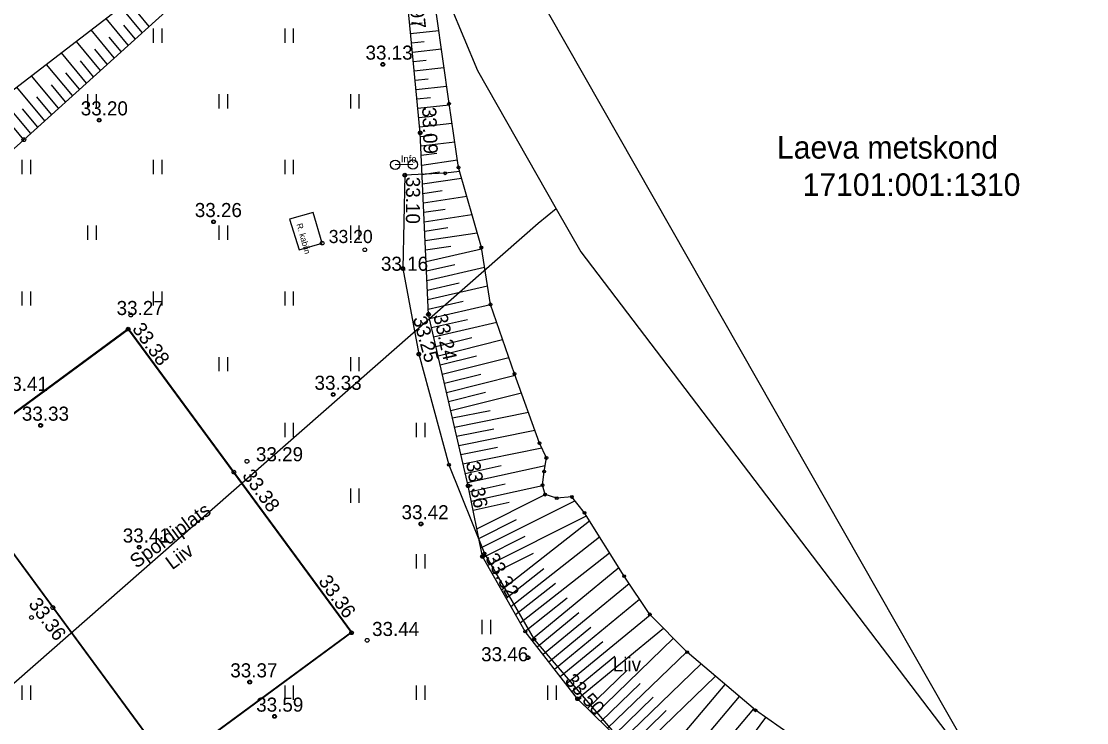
# Model space of a CAD drawing. Extents: x 641898 to 642452, y 6471715 to 6472255.
# Drawn here: x 642067.2 to 642123.9, y 6472154.8 to 6472192.2 of the extents above; entities that cross this region are included whole.
import ezdxf

# ---------------------------------------------------------------- set-up
doc = ezdxf.new("R2010")
doc.units = 0
for name, color, linetype in [('HALJASTUS', 7, 'Continuous'), ('KORGUS-EH2000', 7, 'Continuous'), ('MOOTMPUNKT', 7, 'Continuous'), ('MOOTPIIR', 7, 'Continuous'), ('PIIR', 7, 'Continuous'), ('RAJATIS', 7, 'Continuous'), ('RELJEEF', 7, 'Continuous'), ('VEEKOGU', 7, 'Continuous')]:
    doc.layers.add(name, color=color, linetype=linetype)

msp = doc.modelspace()

# ---------------------------------------------------------------- linework, layer by layer
at = {"layer": 'HALJASTUS'}
for p, q in [((642074.225, 6472191.782), (642074.225, 6472191.021)), ((642074.68, 6472191.782), (642074.68, 6472191.021)), ((642081.225, 6472191.782), (642081.225, 6472191.021)), ((642081.68, 6472191.782), (642081.68, 6472191.021)), ((642070.725, 6472188.282), (642070.725, 6472187.521)), ((642071.18, 6472188.282), (642071.18, 6472187.521)), ((642077.725, 6472188.282), (642077.725, 6472187.521)), ((642078.18, 6472188.282), (642078.18, 6472187.521)), ((642084.725, 6472188.282), (642084.725, 6472187.521)), ((642085.18, 6472188.282), (642085.18, 6472187.521)), ((642067.225, 6472184.782), (642067.225, 6472184.021)), ((642067.68, 6472184.782), (642067.68, 6472184.021)), ((642074.225, 6472184.782), (642074.225, 6472184.021)), ((642074.68, 6472184.782), (642074.68, 6472184.021)), ((642081.225, 6472184.782), (642081.225, 6472184.021)), ((642081.68, 6472184.782), (642081.68, 6472184.021)), ((642070.725, 6472181.282), (642070.725, 6472180.521)), ((642071.18, 6472181.282), (642071.18, 6472180.521)), ((642077.725, 6472181.282), (642077.725, 6472180.521)), ((642078.18, 6472181.282), (642078.18, 6472180.521)), ((642084.725, 6472181.282), (642084.725, 6472180.521)), ((642085.18, 6472181.282), (642085.18, 6472180.521)), ((642067.225, 6472177.782), (642067.225, 6472177.021)), ((642067.68, 6472177.782), (642067.68, 6472177.021)), ((642074.225, 6472177.782), (642074.225, 6472177.021)), ((642074.68, 6472177.782), (642074.68, 6472177.021)), ((642081.225, 6472177.782), (642081.225, 6472177.021)), ((642081.68, 6472177.782), (642081.68, 6472177.021)), ((642077.725, 6472174.282), (642077.725, 6472173.521)), ((642078.18, 6472174.282), (642078.18, 6472173.521)), ((642084.725, 6472174.282), (642084.725, 6472173.521)), ((642085.18, 6472174.282), (642085.18, 6472173.521)), ((642081.225, 6472170.782), (642081.225, 6472170.021)), ((642081.68, 6472170.782), (642081.68, 6472170.021)), ((642088.225, 6472170.782), (642088.225, 6472170.021)), ((642088.68, 6472170.782), (642088.68, 6472170.021)), ((642084.725, 6472167.282), (642084.725, 6472166.521)), ((642085.18, 6472167.282), (642085.18, 6472166.521)), ((642088.225, 6472163.782), (642088.225, 6472163.021)), ((642088.68, 6472163.782), (642088.68, 6472163.021)), ((642091.725, 6472160.282), (642091.725, 6472159.521)), ((642092.18, 6472160.282), (642092.18, 6472159.521)), ((642067.225, 6472156.782), (642067.225, 6472156.021)), ((642067.68, 6472156.782), (642067.68, 6472156.021)), ((642081.225, 6472156.782), (642081.225, 6472156.021)), ((642081.68, 6472156.782), (642081.68, 6472156.021)), ((642088.225, 6472156.782), (642088.225, 6472156.021)), ((642088.68, 6472156.782), (642088.68, 6472156.021)), ((642095.225, 6472156.782), (642095.225, 6472156.021)), ((642095.68, 6472156.782), (642095.68, 6472156.021))]:
    msp.add_line(p, q, dxfattribs=at)
msp.add_lwpolyline([(642090.544, 6472184.173), (642089.776, 6472184.072), (642087.626, 6472183.976), (642087.514, 6472178.998), (642088.366, 6472174.432), (642089.975, 6472168.544), (642091.871, 6472163.809), (642094.517, 6472159.241), (642098.776, 6472154.266), (642105.061, 6472148.666), (642112.911, 6472148.999), (642114.406, 6472149.64)], dxfattribs=at)
at = {"layer": 'KORGUS-EH2000'}
for centre in [(642086.452, 6472189.876), (642071.346, 6472186.906), (642067.331, 6472185.862), (642088.445, 6472186.228), (642087.626, 6472183.976), (642077.439, 6472181.489), (642083.221, 6472180.354), (642085.489, 6472179.997), (642087.514, 6472178.998), (642073.032, 6472176.519), (642088.882, 6472176.556), (642072.887, 6472175.77), (642088.366, 6472174.432), (642083.812, 6472172.286), (642068.226, 6472170.64), (642079.215, 6472168.728), (642078.519, 6472168.152), (642090.992, 6472167.424), (642088.483, 6472165.389), (642073.475, 6472164.147), (642091.756, 6472163.65), (642068.878, 6472160.93), (642067.74, 6472160.405), (642084.787, 6472159.593), (642085.62, 6472159.191), (642094.182, 6472158.265), (642079.361, 6472156.965), (642096.824, 6472156.077), (642080.687, 6472155.138)]:
    msp.add_circle(centre, 0.1, dxfattribs=at)
at = {"layer": 'MOOTMPUNKT'}
for centre in [(642086.452, 6472189.876), (642089.978, 6472187.781), (642071.346, 6472186.906), (642088.445, 6472186.228), (642090.483, 6472184.387), (642087.626, 6472183.976), (642089.776, 6472184.072), (642077.439, 6472181.489), (642091.698, 6472180.112), (642087.514, 6472178.998), (642092.187, 6472177.087), (642088.882, 6472176.556), (642072.875, 6472175.747), (642088.366, 6472174.432), (642093.463, 6472173.395), (642083.812, 6472172.286), (642068.226, 6472170.64), (642094.796, 6472169.693), (642095.162, 6472168.903), (642089.975, 6472168.544), (642095.04, 6472168.192), (642090.992, 6472167.424), (642094.951, 6472167.46), (642095.102, 6472166.95), (642095.71, 6472166.763), (642096.522, 6472166.827), (642097.188, 6472165.98), (642088.483, 6472165.389), (642073.475, 6472164.147), (642091.756, 6472163.65), (642091.871, 6472163.809), (642099.309, 6472162.605), (642100.668, 6472160.571), (642084.776, 6472159.609), (642094.039, 6472159.656), (642094.517, 6472159.241), (642102.657, 6472158.561), (642094.182, 6472158.265), (642079.361, 6472156.965), (642096.824, 6472156.077), (642080.687, 6472155.138), (642106.307, 6472155.459)]:
    msp.add_circle(centre, 0.075, dxfattribs=at)
at = {"layer": 'MOOTPIIR'}
msp.add_lwpolyline([(642014.306, 6472085.384), (642027.67, 6472104.979), (642055.501, 6472084.843), (642081.563, 6472094.262), (642123.938, 6472142.273), (642065.721, 6472244.475), (642008.922, 6472196.948), (642003.347, 6472200.453), (641979.65, 6472162.756), (641979.65, 6472162.756), (641986.045, 6472158.736), (642004.269, 6472142.365), (641987.048, 6472123.488), (641970.482, 6472097.889), (641986.758, 6472084.396)], close=True, dxfattribs=at)
at = {"layer": 'PIIR'}
for p, q in [((642090.03, 6472193.03), (642091.5, 6472189.54)), ((642091.5, 6472189.54), (642095.69, 6472182.18)), ((642095.69, 6472182.18), (642094.72, 6472181.39)), ((642095.69, 6472182.18), (642097, 6472179.89)), ((642094.72, 6472181.39), (642016.19, 6472112.51)), ((642097, 6472179.89), (642121.79, 6472147.29))]:
    msp.add_line(p, q, dxfattribs=at)
at = {"layer": 'RAJATIS'}
for points in [[(642088.054, 6472184.539), (642087.113, 6472184.528)], [(642081.989, 6472179.992), (642083.221, 6472180.354), (642082.742, 6472181.977), (642081.489, 6472181.633), (642081.989, 6472179.992)], [(642084.764, 6472159.611), (642075.113, 6472152.507), (642063.231, 6472168.648), (642072.882, 6472175.752), (642084.764, 6472159.611)]]:
    msp.add_lwpolyline(points, dxfattribs=at)
msp.add_lwpolyline([(642072.888, 6472175.794), (642084.806, 6472159.604), (642075.107, 6472152.465), (642063.189, 6472168.655)], close=True, dxfattribs=at)
for centre in [(642087.113, 6472184.528), (642088.054, 6472184.539)]:
    msp.add_circle(centre, 0.25, dxfattribs=at)
at = {"layer": 'RELJEEF'}
for p, q in [((642073.634, 6472191.565), (642072.509, 6472192.93)), ((642072.891, 6472190.893), (642071.716, 6472192.32)), ((642074.005, 6472191.901), (642073.429, 6472192.599)), ((642072.149, 6472190.221), (642070.923, 6472191.709)), ((642073.263, 6472191.229), (642072.658, 6472191.963)), ((642087.884, 6472192.017), (642088.542, 6472192.09)), ((642087.932, 6472191.519), (642089.43, 6472191.685)), ((642071.407, 6472189.55), (642070.13, 6472191.099)), ((642072.52, 6472190.557), (642071.886, 6472191.327)), ((642087.98, 6472191.022), (642088.652, 6472191.096)), ((642070.665, 6472188.878), (642069.337, 6472190.489)), ((642071.778, 6472189.886), (642071.114, 6472190.691)), ((642088.029, 6472190.524), (642089.569, 6472190.695)), ((642069.926, 6472188.21), (642068.541, 6472189.876)), ((642071.036, 6472189.214), (642070.342, 6472190.055)), ((642088.077, 6472190.026), (642088.762, 6472190.102)), ((642069.184, 6472187.538), (642067.748, 6472189.266)), ((642070.297, 6472188.546), (642069.571, 6472189.419)), ((642088.125, 6472189.528), (642089.708, 6472189.704)), ((642069.555, 6472187.874), (642068.802, 6472188.78)), ((642088.174, 6472189.027), (642088.874, 6472189.108)), ((642088.222, 6472188.529), (642089.847, 6472188.718)), ((642068.444, 6472186.869), (642066.952, 6472188.653)), ((642068.813, 6472187.203), (642068.033, 6472188.141)), ((642067.702, 6472186.198), (642066.159, 6472188.043)), ((642088.27, 6472188.032), (642088.989, 6472188.115)), ((642088.318, 6472187.534), (642089.986, 6472187.727)), ((642068.073, 6472186.534), (642067.265, 6472187.5)), ((642088.367, 6472187.036), (642089.104, 6472187.122)), ((642067.331, 6472185.862), (642066.498, 6472186.858)), ((642088.415, 6472186.538), (642090.133, 6472186.738)), ((642088.454, 6472186.039), (642089.22, 6472186.128)), ((642088.476, 6472185.539), (642090.28, 6472185.748)), ((642088.499, 6472185.038), (642089.335, 6472185.135)), ((642088.523, 6472184.507), (642090.423, 6472184.794)), ((642088.545, 6472184.005), (642089.47, 6472184.144)), ((642088.568, 6472183.503), (642090.645, 6472183.816)), ((642088.591, 6472183.001), (642089.619, 6472183.155)), ((642088.614, 6472182.498), (642090.921, 6472182.846)), ((642088.636, 6472181.996), (642089.768, 6472182.167)), ((642088.659, 6472181.494), (642091.197, 6472181.876)), ((642088.682, 6472180.992), (642089.917, 6472181.178)), ((642088.704, 6472180.489), (642091.472, 6472180.907)), ((642088.727, 6472179.987), (642090.066, 6472180.189)), ((642088.755, 6472179.376), (642091.708, 6472180.052)), ((642088.778, 6472178.868), (642090.286, 6472179.214)), ((642088.8, 6472178.361), (642091.868, 6472179.063)), ((642088.823, 6472177.853), (642090.509, 6472178.239)), ((642088.846, 6472177.345), (642092.028, 6472178.074)), ((642088.869, 6472176.838), (642090.732, 6472177.264)), ((642088.932, 6472176.339), (642092.188, 6472177.084)), ((642089.045, 6472175.852), (642090.955, 6472176.289)), ((642089.157, 6472175.365), (642092.516, 6472176.134)), ((642089.279, 6472174.837), (642091.189, 6472175.317)), ((642089.392, 6472174.35), (642092.834, 6472175.215)), ((642089.504, 6472173.862), (642091.432, 6472174.347)), ((642089.617, 6472173.375), (642093.162, 6472174.266)), ((642089.73, 6472172.888), (642091.676, 6472173.377)), ((642089.842, 6472172.401), (642093.491, 6472173.318)), ((642089.955, 6472171.913), (642091.92, 6472172.407)), ((642090.067, 6472171.426), (642093.831, 6472172.372)), ((642090.157, 6472171.036), (642092.162, 6472171.437)), ((642090.27, 6472170.549), (642094.204, 6472171.336)), ((642090.383, 6472170.062), (642092.358, 6472170.457)), ((642090.495, 6472169.574), (642094.547, 6472170.384)), ((642090.608, 6472169.087), (642092.554, 6472169.476)), ((642090.72, 6472168.599), (642094.914, 6472169.438)), ((642090.841, 6472168.076), (642092.758, 6472168.497)), ((642090.954, 6472167.589), (642095.092, 6472168.498)), ((642091.058, 6472167.1), (642092.972, 6472167.52)), ((642091.157, 6472166.61), (642094.956, 6472167.444)), ((642091.457, 6472165.126), (642095.101, 6472166.953)), ((642091.663, 6472164.111), (642096.68, 6472166.625)), ((642091.256, 6472166.12), (642093.186, 6472166.543)), ((642091.56, 6472164.618), (642093.576, 6472165.629)), ((642092.028, 6472163.175), (642097.293, 6472165.814)), ((642092.771, 6472161.875), (642097.453, 6472165.558)), ((642091.779, 6472163.61), (642094.024, 6472164.735)), ((642093.272, 6472160.997), (642097.988, 6472164.707)), ((642092.276, 6472162.74), (642094.472, 6472163.841)), ((642093.774, 6472160.12), (642098.523, 6472163.855)), ((642093.021, 6472161.436), (642095.033, 6472163.019)), ((642094.369, 6472159.232), (642099.02, 6472163.065)), ((642093.523, 6472160.559), (642095.652, 6472162.233)), ((642094.983, 6472158.443), (642099.566, 6472162.22)), ((642094.025, 6472159.681), (642096.27, 6472161.447)), ((642095.597, 6472157.653), (642100.125, 6472161.384)), ((642094.676, 6472158.838), (642096.897, 6472160.668)), ((642096.212, 6472156.864), (642100.687, 6472160.552)), ((642095.29, 6472158.048), (642097.533, 6472159.896)), ((642096.826, 6472156.075), (642101.393, 6472159.838)), ((642097.711, 6472155.208), (642101.931, 6472159.295)), ((642095.905, 6472157.259), (642098.169, 6472159.125)), ((642096.519, 6472156.469), (642098.805, 6472158.353)), ((642098.426, 6472154.508), (642102.634, 6472158.584)), ((642097.354, 6472155.558), (642099.462, 6472157.6)), ((642099.141, 6472153.808), (642103.397, 6472157.932)), ((642099.856, 6472153.108), (642104.163, 6472157.281)), ((642098.069, 6472154.858), (642100.158, 6472156.881)), ((642100.778, 6472152.205), (642104.679, 6472156.842)), ((642098.783, 6472154.158), (642100.853, 6472156.163)), ((642101.558, 6472151.579), (642105.441, 6472156.195)), ((642099.498, 6472153.458), (642101.549, 6472155.445)), ((642102.339, 6472150.953), (642106.203, 6472155.547)), ((642103.266, 6472150.211), (642106.846, 6472155.082))]:
    msp.add_line(p, q, dxfattribs=at)
msp.add_lwpolyline([(642120.985, 6472144.502), (642117.979, 6472144.088), (642110.518, 6472146.231), (642105.506, 6472148.417), (642100.785, 6472152.198), (642096.824, 6472156.077), (642094.039, 6472159.656), (642091.756, 6472163.65), (642090.992, 6472167.424), (642088.882, 6472176.556), (642088.445, 6472186.228), (642087.656, 6472194.367), (642088.054, 6472200.65), (642087.81, 6472201.434), (642086.987, 6472201.809), (642085.827, 6472201.697), (642084.8, 6472201.227), (642084.408, 6472200.976), (642075.818, 6472193.541), (642067.331, 6472185.862), (642054.685, 6472174.531), (642049.809, 6472171.194), (642046.347, 6472166.588), (642038.018, 6472156.193)], dxfattribs=at)
at = {"layer": 'VEEKOGU'}
for points in [[(642084.499, 6472202.158), (642059.755, 6472183.114), (642051.716, 6472175.574), (642047.81, 6472174.009), (642043.609, 6472168.925), (642039.566, 6472171.285), (642040.101, 6472172.469), (642040.135, 6472175.575), (642038.525, 6472177.127)], [(642109.59, 6472153.163), (642106.307, 6472155.459), (642102.657, 6472158.561), (642100.668, 6472160.571), (642099.309, 6472162.605), (642097.188, 6472165.98), (642096.522, 6472166.827), (642095.71, 6472166.763), (642095.102, 6472166.95), (642094.951, 6472167.46), (642095.04, 6472168.192), (642095.162, 6472168.903), (642094.796, 6472169.693), (642093.463, 6472173.395), (642092.187, 6472177.087), (642091.698, 6472180.112), (642090.483, 6472184.387), (642089.978, 6472187.781), (642089.31, 6472192.543)]]:
    msp.add_lwpolyline(points, dxfattribs=at)

# ---------------------------------------------------------------- texts
at = {"layer": 'HALJASTUS'}
msp.add_text('Liiv', height=0.75, dxfattribs=at).set_placement((642098.698, 6472157.532))
at = {"layer": 'KORGUS-EH2000'}
for s, rotation, p in [('32.97', 275.9235, (642087.751, 6472194.24)), ('33.09', 272.0653, (642088.544, 6472187.594)), ('33.10', 269.8736, (642087.686, 6472183.886)), ('33.25', 285.6164, (642088.042, 6472176.344)), ('33.24', 282.8195, (642089.133, 6472176.493)), ('33.38', 306.1205, (642073.071, 6472175.775)), ('33.38', 306.3591, (642078.931, 6472167.963)), ('33.36', 280.0938, (642090.879, 6472168.655)), ('33.32', 298.9483, (642091.883, 6472163.577)), ('33.36', 305.6784, (642082.991, 6472162.334)), ('33.36', 306.397, (642067.548, 6472161.114)), ('33.50', 311.8156, (642096.098, 6472157.006))]:
    msp.add_text(s, height=0.75, rotation=rotation, dxfattribs=at).set_placement(p)
for s, height, p in [('33.13', 0.75, (642085.529, 6472190.126)), ('33.20', 0.75, (642070.364, 6472187.156)), ('33.26', 0.75, (642076.437, 6472181.739)), ('33.20', 0.7, (642083.571, 6472180.354)), ('33.16', 0.75, (642086.352, 6472178.878)), ('33.27', 0.75, (642072.274, 6472176.519)), ('33.41', 0.75, (642066.106, 6472172.48)), ('33.33', 0.75, (642082.814, 6472172.536)), ('33.33', 0.75, (642067.228, 6472170.89)), ('33.29', 0.75, (642079.694, 6472168.728)), ('33.42', 0.75, (642087.448, 6472165.639)), ('33.41', 0.75, (642072.601, 6472164.397)), ('33.44', 0.75, (642085.879, 6472159.42)), ('33.46', 0.75, (642091.688, 6472158.073)), ('33.37', 0.75, (642078.328, 6472157.215)), ('33.59', 0.75, (642079.707, 6472155.388))]:
    msp.add_text(s, height=height, dxfattribs=at).set_placement(p)
at = {"layer": 'PIIR'}
for s, p in [('Laeva metskond', (642107.442, 6472184.852)), ('17101:001:1310', (642108.807, 6472182.868))]:
    msp.add_text(s, height=1.2, dxfattribs=at).set_placement(p)
at = {"layer": 'RAJATIS'}
msp.add_text('Info', height=0.375, dxfattribs=at).set_placement((642087.413, 6472184.647))
for s, height, rotation, p in [('R. kabiin', 0.3228, 285.9061, (642081.847, 6472181.354)), ('Spordiplats', 0.75, 36.3571, (642073.329, 6472162.991)), ('Liiv', 0.75, 36.3571, (642075.232, 6472162.916))]:
    msp.add_text(s, height=height, rotation=rotation, dxfattribs=at).set_placement(p)

doc.saveas('drawing.dxf')
